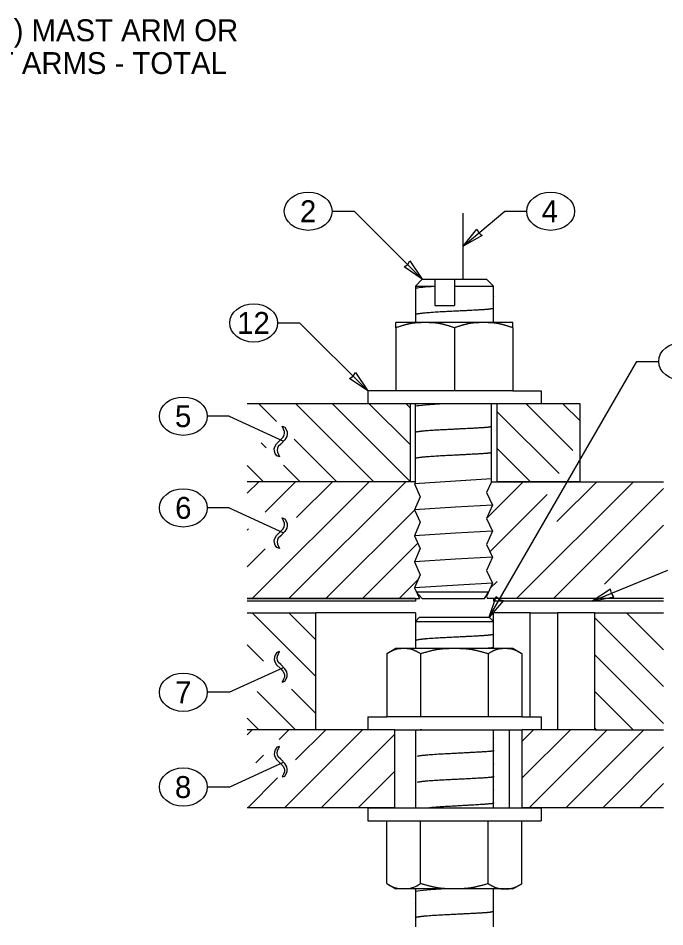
# Model space of a CAD drawing. Extents: x 99862 to 103151, y 100000 to 102076.
# Drawn here: x 100335 to 100807, y 100763 to 101428 of the extents above; entities that cross this region are included whole.
import ezdxf

# ---------------------------------------------------------------- set-up
doc = ezdxf.new("R2010")
doc.units = 0
for name, color, linetype in [('Level 15', 7, 'Continuous'), ('Level 2', 7, 'Continuous'), ('Level 20', 7, 'Continuous'), ('Level 3', 7, 'Continuous'), ('Level 4', 7, 'Continuous'), ('Level 6', 7, 'Continuous'), ('Level 62', 7, 'Continuous'), ('Level 7', 7, 'Continuous'), ('Level 9', 7, 'Continuous')]:
    doc.layers.add(name, color=color, linetype=linetype)

msp = doc.modelspace()

# ---------------------------------------------------------------- linework, layer by layer
at = {"layer": 'Level 15'}
for p, q in [((100563.94, 101286.35), (100579.94, 101286.35)), ((100579.94, 101286.35), (100629.78, 101236.72)), ((100659.59, 101260.86), (100690.09, 101286.35)), ((100690.09, 101286.35), (100706.09, 101286.35)), ((100524.09, 101204.68), (100540.09, 101204.68)), ((100540.09, 101204.68), (100589.94, 101155.05)), ((100678.61, 100989.53), (100786.59, 101176.57)), ((100786.59, 101176.57), (100802.59, 101176.57)), ((100488.68, 101136.47), (100472.68, 101136.47)), ((100488.68, 101136.47), (100528.5, 101118.31)), ((100488.68, 101069.43), (100472.68, 101069.43)), ((100488.68, 101069.43), (100528.5, 101051.27)), ((100754.07, 101001.27), (100809.22, 101023.82)), ((100488.68, 100934.6), (100528.5, 100952.76)), ((100488.68, 100934.6), (100472.68, 100934.6)), ((100488.68, 100865.26), (100528.5, 100883.43)), ((100488.68, 100865.26), (100472.68, 100865.26))]:
    msp.add_line(p, q, dxfattribs=at)
for points in [[(100659.59, 101260.86), (100669.68, 101273.31), (100671.09, 101270.47), (100673.63, 101268.57)], [(100629.78, 101236.72), (100616.47, 101245.63), (100619.16, 101247.3), (100620.82, 101250)], [(100589.94, 101155.05), (100576.62, 101163.96), (100579.31, 101165.63), (100580.97, 101168.33)], [(100754.07, 101001.27), (100769.8, 101004.37), (100767.96, 101006.95), (100767.46, 101010.08)], [(100678.61, 100989.53), (100683.8, 101004.69), (100686.1, 101002.51), (100689.14, 101001.6)]]:
    msp.add_lwpolyline(points, close=True, dxfattribs=at)
at = {"layer": 'Level 2'}
for p, q in [((100624.77, 101003.05), (100501.89, 101003.05)), ((100624.77, 101001.27), (100501.89, 101001.27)), ((100624.77, 101003.05), (100624.77, 101001.27)), ((100681.76, 101003.05), (100681.76, 101001.27)), ((100806.13, 101003.05), (100681.76, 101003.05)), ((100806.13, 101001.27), (100681.76, 101001.27))]:
    msp.add_line(p, q, dxfattribs=at)
at = {"layer": 'Level 20'}
for p, q in [((100528.5, 101126.96), (100527.36, 101129.1)), ((100527.36, 101129.1), (100529.35, 101128.39)), ((100529.35, 101128.39), (100530.43, 101126.73)), ((100526.15, 101119.19), (100527.94, 101121.01)), ((100527.94, 101121.01), (100528.91, 101122.66)), ((100529.08, 101125.33), (100528.5, 101126.96)), ((100528.91, 101122.66), (100529.17, 101123.97)), ((100529.17, 101123.97), (100529.08, 101125.33)), ((100530.78, 101121.61), (100529.43, 101119.25)), ((100530.43, 101126.73), (100531.04, 101125.04)), ((100531.15, 101123.34), (100530.78, 101121.61)), ((100531.04, 101125.04), (100531.15, 101123.34)), ((100521.68, 101112.54), (100522.04, 101114.17)), ((100522.04, 101114.17), (100523.21, 101116.34)), ((100523.21, 101116.34), (100526.15, 101119.19)), ((100524.62, 101114.39), (100523.9, 101113.08)), ((100526.33, 101116.12), (100524.62, 101114.39)), ((100529.43, 101119.25), (100526.33, 101116.12)), ((100521.8, 101110.93), (100521.68, 101112.54)), ((100522.38, 101109.25), (100521.8, 101110.93)), ((100523.48, 101107.41), (100522.38, 101109.25)), ((100525.47, 101106.7), (100523.48, 101107.41)), ((100523.9, 101113.08), (100523.67, 101111.68)), ((100523.67, 101111.68), (100523.91, 101110.05)), ((100523.91, 101110.05), (100525.47, 101106.7)), ((100528.5, 101059.92), (100527.36, 101062.06)), ((100527.36, 101062.06), (100529.35, 101061.35)), ((100529.35, 101061.35), (100530.43, 101059.68)), ((100526.15, 101052.14), (100527.94, 101053.96)), ((100527.94, 101053.96), (100528.91, 101055.62)), ((100529.08, 101058.28), (100528.5, 101059.92)), ((100528.91, 101055.62), (100529.17, 101056.93)), ((100529.17, 101056.93), (100529.08, 101058.28)), ((100530.78, 101054.57), (100529.43, 101052.21)), ((100530.43, 101059.68), (100531.04, 101058)), ((100531.15, 101056.29), (100530.78, 101054.57)), ((100531.04, 101058), (100531.15, 101056.29)), ((100522.04, 101047.13), (100523.21, 101049.3)), ((100523.21, 101049.3), (100526.15, 101052.14)), ((100524.62, 101047.35), (100523.9, 101046.04)), ((100526.33, 101049.07), (100524.62, 101047.35)), ((100529.43, 101052.21), (100526.33, 101049.07)), ((100521.68, 101045.5), (100522.04, 101047.13)), ((100521.8, 101043.89), (100521.68, 101045.5)), ((100522.38, 101042.21), (100521.8, 101043.89)), ((100523.48, 101040.37), (100522.38, 101042.21)), ((100523.9, 101046.04), (100523.67, 101044.64)), ((100523.67, 101044.64), (100523.91, 101043.01)), ((100523.91, 101043.01), (100525.47, 101039.66)), ((100525.47, 101039.66), (100523.48, 101040.37)), ((100522.38, 100961.82), (100521.8, 100960.14)), ((100523.48, 100963.66), (100522.38, 100961.82)), ((100525.47, 100964.37), (100523.48, 100963.66)), ((100523.67, 100959.39), (100523.91, 100961.02)), ((100523.91, 100961.02), (100525.47, 100964.37)), ((100521.8, 100960.14), (100521.68, 100958.53)), ((100521.68, 100958.53), (100522.04, 100956.9)), ((100522.04, 100956.9), (100523.21, 100954.73)), ((100523.21, 100954.73), (100526.15, 100951.89)), ((100523.9, 100957.99), (100523.67, 100959.39)), ((100524.62, 100956.68), (100523.9, 100957.99)), ((100526.33, 100954.96), (100524.62, 100956.68)), ((100529.43, 100951.82), (100526.33, 100954.96)), ((100526.15, 100951.89), (100527.94, 100950.07)), ((100527.94, 100950.07), (100528.91, 100948.41)), ((100528.91, 100948.41), (100529.17, 100947.1)), ((100530.78, 100949.46), (100529.43, 100951.82)), ((100531.15, 100947.73), (100530.78, 100949.46)), ((100531.04, 100946.03), (100531.15, 100947.73)), ((100528.5, 100944.11), (100527.36, 100941.97)), ((100527.36, 100941.97), (100529.35, 100942.68)), ((100529.08, 100945.75), (100528.5, 100944.11)), ((100529.17, 100947.1), (100529.08, 100945.75)), ((100529.35, 100942.68), (100530.43, 100944.35)), ((100530.43, 100944.35), (100531.04, 100946.03)), ((100525.47, 100895.04), (100523.48, 100894.33)), ((100523.91, 100891.69), (100525.47, 100895.04)), ((100521.8, 100890.81), (100521.68, 100889.19)), ((100521.68, 100889.19), (100522.04, 100887.57)), ((100522.38, 100892.49), (100521.8, 100890.81)), ((100523.48, 100894.33), (100522.38, 100892.49)), ((100523.67, 100890.06), (100523.91, 100891.69)), ((100523.9, 100888.66), (100523.67, 100890.06)), ((100524.62, 100887.34), (100523.9, 100888.66)), ((100522.04, 100887.57), (100523.21, 100885.4)), ((100523.21, 100885.4), (100526.15, 100882.55)), ((100526.33, 100885.62), (100524.62, 100887.34)), ((100526.15, 100882.55), (100527.94, 100880.73)), ((100529.43, 100882.49), (100526.33, 100885.62)), ((100530.78, 100880.12), (100529.43, 100882.49)), ((100528.5, 100874.78), (100527.36, 100872.64)), ((100527.94, 100880.73), (100528.91, 100879.08)), ((100529.08, 100876.41), (100528.5, 100874.78)), ((100528.91, 100879.08), (100529.17, 100877.77)), ((100529.17, 100877.77), (100529.08, 100876.41)), ((100529.35, 100873.35), (100530.43, 100875.01)), ((100530.43, 100875.01), (100531.04, 100876.7)), ((100531.15, 100878.4), (100530.78, 100880.12)), ((100531.04, 100876.7), (100531.15, 100878.4)), ((100527.36, 100872.64), (100529.35, 100873.35))]:
    msp.add_line(p, q, dxfattribs=at)
for centre in [(100546.44, 101286.35), (100723.59, 101286.35), (100506.59, 101204.68), (100820.09, 101176.57), (100455.18, 101136.47), (100455.18, 101069.43), (100455.18, 100934.6), (100455.18, 100865.26)]:
    msp.add_ellipse(centre, major_axis=(-17.5, 0), ratio=0.8, dxfattribs=at)
at = {"layer": 'Level 3'}
for p, q in [((100624.77, 101088.55), (100501.89, 101088.55)), ((100501.89, 101080.07), (100510.37, 101088.55)), ((100505.48, 101003.05), (100590.98, 101088.55)), ((100514.94, 101066.25), (100537.24, 101088.55)), ((100532.35, 101003.05), (100617.85, 101088.55)), ((100537.96, 101062.4), (100564.11, 101088.55)), ((100624.77, 101088.55), (100624.11, 101087.09)), ((100680.41, 101088.55), (100676.83, 101080.61)), ((100676.98, 101061.92), (100703.61, 101088.55)), ((100680.41, 101088.55), (100806.13, 101088.55)), ((100698.72, 101003.05), (100784.21, 101088.55)), ((100728.17, 101059.38), (100757.34, 101088.55)), ((100624.11, 101087.09), (100628.38, 101077.59)), ((100676.83, 101080.61), (100681.11, 101071.33)), ((100725.59, 101003.05), (100806.13, 101083.6)), ((100628.38, 101077.59), (100624.11, 101068.07)), ((100679.27, 101037.34), (100721.16, 101079.24)), ((100559.22, 101003.05), (100624.77, 101068.6)), ((100624.11, 101068.07), (100628.38, 101058.86)), ((100681.11, 101071.33), (100676.83, 101061.59)), ((100676.83, 101061.59), (100681.11, 101052.37)), ((100501.89, 101053.2), (100502.86, 101054.17)), ((100628.38, 101058.86), (100624.11, 101049.03)), ((100762.94, 101013.54), (100806.13, 101056.73)), ((100624.11, 101049.03), (100628.38, 101039.82)), ((100681.11, 101052.37), (100676.83, 101042.62)), ((100586.09, 101003.05), (100626.63, 101043.6)), ((100676.83, 101042.62), (100681.11, 101033.34)), ((100501.89, 101026.33), (100514.93, 101039.37)), ((100628.38, 101039.82), (100624.11, 101030.07)), ((100624.11, 101030.07), (100628.38, 101020.57)), ((100681.11, 101033.34), (100676.83, 101023.59)), ((100676.83, 101023.59), (100681.11, 101014.4)), ((100612.96, 101003.05), (100626.68, 101016.78)), ((100628.38, 101020.57), (100624.11, 101011.04)), ((100681.11, 101014.4), (100676.83, 101004.57)), ((100679.5, 101010.71), (100684.46, 101015.67)), ((100624.11, 101011.04), (100627.71, 101003.05)), ((100501.89, 101003.05), (100627.71, 101003.05)), ((100676.83, 101004.57), (100677.54, 101003.05)), ((100806.13, 101003.05), (100677.54, 101003.05)), ((100501.89, 100992.66), (100552.03, 100992.66)), ((100552.03, 100907.17), (100552.03, 100992.66)), ((100755.89, 100907.17), (100755.89, 100992.66)), ((100755.89, 100992.66), (100806.13, 100992.66)), ((100552.03, 100907.17), (100501.89, 100907.17)), ((100755.89, 100907.17), (100806.13, 100907.17))]:
    msp.add_line(p, q, dxfattribs=at)
at = {"layer": 'Level 4'}
for p, q in [((100501.89, 100903.54), (100505.52, 100907.17)), ((100525.17, 100899.95), (100532.39, 100907.17)), ((100529.13, 100850.17), (100586.13, 100907.17)), ((100537.17, 100885.08), (100559.26, 100907.17)), ((100609.7, 100907.17), (100552.03, 100907.17)), ((100556, 100850.17), (100609.7, 100903.87)), ((100609.7, 100850.17), (100609.7, 100907.17)), ((100693.57, 100850.17), (100693.57, 100907.17)), ((100755.89, 100907.17), (100702.9, 100907.17)), ((100702.9, 100850.17), (100702.9, 100907.17)), ((100702.9, 100898.92), (100711.15, 100907.17)), ((100702.9, 100872.05), (100738.02, 100907.17)), ((100707.89, 100850.17), (100764.89, 100907.17)), ((100734.76, 100850.17), (100791.76, 100907.17)), ((100761.63, 100850.17), (100806.13, 100894.67)), ((100508.17, 100882.95), (100513.79, 100888.57)), ((100582.87, 100850.17), (100609.7, 100877)), ((100502.26, 100850.17), (100524.09, 100872)), ((100788.5, 100850.17), (100806.13, 100867.8)), ((100609.7, 100850.17), (100501.89, 100850.17)), ((100806.13, 100850.17), (100702.9, 100850.17))]:
    msp.add_line(p, q, dxfattribs=at)
at = {"layer": 'Level 6'}
msp.add_line((100682.1, 100764), (100681.74, 100763.93), dxfattribs=at)
at = {"layer": 'Level 62'}
for points in [[(100680.41, 101090.57), (100624.13, 101087.13)], [(100681.11, 101071.33), (100654.11, 101069.92), (100624.11, 101068.07)], [(100681.11, 101052.37), (100654.07, 101050.92), (100624.11, 101049.03)], [(100681.11, 101033.34), (100653.99, 101031.9), (100624.11, 101030.07)], [(100681.11, 101014.4), (100655.94, 101013.01), (100624.11, 101011.04)]]:
    msp.add_lwpolyline(points, dxfattribs=at)
for points, degree in [([(100639, 101231.3), (100631.68, 101230.82), (100627.1, 101230.4), (100625.47, 101230.04)], 3), ([(100681.74, 101224.33), (100681.89, 101224.24), (100681.89, 101224.15), (100681.74, 101224.05)], 3), ([(100681.05, 101215.08), (100679.43, 101214.69), (100675.63, 101214.37), (100670.57, 101214.1), (100652.29, 101213.09), (100630.39, 101212.14), (100625.47, 101211.02)], 4), ([(100681.74, 101205.31), (100681.93, 101205.18), (100681.84, 101205.05), (100681.49, 101204.92)], 3), ([(100646.7, 101145.55), (100635.04, 101144.86), (100627.17, 101144.27), (100624.83, 101143.76)], 3), ([(100680.41, 101128.77), (100678.55, 101128.31), (100673.86, 101127.95), (100667.71, 101127.65), (100649.66, 101126.71), (100629.45, 101125.75), (100624.83, 101124.73)], 4), ([(100680.41, 101109.79), (100678.65, 101109.36), (100674.32, 101109.01), (100668.62, 101108.73), (100650.46, 101107.76), (100629.57, 101106.73), (100624.83, 101105.7)], 4), ([(100681.05, 100976.7), (100679.43, 100976.31), (100675.63, 100975.99), (100670.57, 100975.72), (100652.29, 100974.71), (100630.39, 100973.76), (100625.47, 100972.64)], 4), ([(100681.74, 100967.74), (100682.43, 100967.26), (100679.73, 100966.87), (100674.76, 100966.54)], 3), ([(100629.38, 100907.17), (100627.83, 100907.01), (100626.77, 100906.86), (100626.16, 100906.73)], 3), ([(100681.74, 100901.23), (100681.87, 100901.15), (100681.87, 100901.06), (100681.74, 100900.97)], 3), ([(100682.43, 100892), (100681.68, 100891.52), (100677.63, 100891.13), (100671.72, 100890.82), (100653.45, 100889.79), (100631.23, 100888.78), (100626.16, 100887.7)], 4), ([(100681.74, 100891.73), (100681.84, 100891.65), (100681.84, 100891.57), (100681.74, 100891.5)], 3), ([(100681.74, 100882.25), (100681.87, 100882.16), (100681.87, 100882.08), (100681.74, 100881.99)], 3), ([(100682.43, 100872.98), (100681.6, 100872.45), (100677.02, 100872.02), (100670.41, 100871.66), (100652.18, 100870.68), (100630.92, 100869.74), (100626.16, 100868.68)], 4), ([(100681.74, 100872.74), (100681.88, 100872.65), (100681.88, 100872.56), (100681.74, 100872.47)], 3), ([(100681.74, 100863.22), (100681.88, 100863.13), (100681.88, 100863.04), (100681.74, 100862.95)], 3), ([(100681.74, 100853.72), (100682.28, 100853.34), (100680.52, 100853.04), (100677.18, 100852.78), (100667.62, 100852.05), (100649.74, 100851.2), (100635.17, 100850.17)], 4), ([(100624.75, 100789.62), (100624.66, 100789.57), (100624.66, 100789.51), (100624.75, 100789.45)], 3), ([(100647.77, 100790.8), (100635.91, 100790.09), (100627.78, 100789.45), (100625.43, 100788.89)], 3), ([(100624.75, 100780.16), (100624.61, 100780.1), (100624.6, 100780.03), (100624.75, 100779.95)], 3), ([(100624.75, 100770.65), (100624.67, 100770.6), (100624.67, 100770.54), (100624.75, 100770.48)], 3), ([(100681.01, 100773.99), (100679.15, 100773.54), (100674.46, 100773.18), (100668.31, 100772.88), (100650.25, 100771.94), (100630.05, 100770.97), (100625.43, 100769.96)], 4)]:
    msp.add_open_spline(points, degree=degree, dxfattribs=at)
at = {"layer": 'Level 7'}
for p, q in [((100505.42, 100992.66), (100552.03, 100946.05)), ((100532.29, 100992.66), (100552.03, 100972.92)), ((100708.68, 100992.66), (100681.74, 100992.66)), ((100708.68, 100916.67), (100708.68, 100992.66)), ((100708.68, 100992.66), (100728.83, 100992.66)), ((100728.83, 100907.17), (100728.83, 100992.66)), ((100755.89, 100992.66), (100728.83, 100992.66)), ((100755.89, 100988.95), (100806.13, 100938.71)), ((100779.04, 100992.66), (100806.13, 100965.57)), ((100805.91, 100992.66), (100806.13, 100992.44)), ((100501.89, 100969.32), (100513.83, 100957.39)), ((100755.89, 100962.08), (100806.13, 100911.84)), ((100509.19, 100935.16), (100537.18, 100907.17)), ((100534.29, 100936.92), (100552.03, 100919.18)), ((100755.89, 100935.22), (100783.93, 100907.17)), ((100501.89, 100915.59), (100510.31, 100907.17)), ((100755.89, 100908.35), (100757.06, 100907.17))]:
    msp.add_line(p, q, dxfattribs=at)
at = {"layer": 'Level 9'}
for p, q in [((100659.59, 101236.72), (100659.59, 101284.99)), ((100629.78, 101236.72), (100624.75, 101231.68)), ((100629.78, 101236.72), (100659.59, 101236.72)), ((100639, 101236.72), (100639, 101217.43)), ((100653.25, 101236.72), (100653.25, 101217.43)), ((100659.59, 101236.72), (100676.71, 101236.72)), ((100681.74, 101231.68), (100676.71, 101236.72)), ((100624.75, 101231.68), (100624.75, 101204.92)), ((100624.75, 101231.68), (100639, 101231.68)), ((100653.25, 101231.68), (100681.74, 101231.68)), ((100681.74, 101204.92), (100681.74, 101231.68)), ((100639, 101217.43), (100653.25, 101217.43)), ((100681.74, 101204.92), (100610.53, 101204.92)), ((100610.53, 101201.11), (100610.53, 101155.05)), ((100632.91, 101204.92), (100630.89, 101204.92)), ((100653.27, 101201.11), (100653.27, 101155.05)), ((100675.41, 101204.92), (100673.86, 101204.92)), ((100696.01, 101204.92), (100681.74, 101204.92)), ((100696.01, 101201.1), (100696.01, 101155.05)), ((100589.94, 101155.05), (100589.94, 101145.55)), ((100696.01, 101155.05), (100589.94, 101155.05)), ((100696.01, 101155.05), (100716.6, 101155.05)), ((100716.6, 101155.05), (100716.6, 101155.05)), ((100716.6, 101155.05), (100716.6, 101145.55)), ((100589.94, 101145.55), (100501.89, 101145.55)), ((100510.46, 101145.55), (100523.38, 101132.63)), ((100537.33, 101145.55), (100594.33, 101088.55)), ((100564.2, 101145.55), (100621.19, 101088.55)), ((100621.21, 101145.55), (100589.94, 101145.55)), ((100591.07, 101145.55), (100621.21, 101115.41)), ((100617.93, 101145.55), (100621.21, 101142.28)), ((100684.62, 101145.55), (100621.21, 101145.55)), ((100621.21, 101088.55), (100621.21, 101145.55)), ((100624.77, 101088.55), (100624.77, 101145.55)), ((100680.41, 101088.55), (100680.41, 101145.55)), ((100684.62, 101088.55), (100684.62, 101145.55)), ((100716.6, 101145.55), (100684.62, 101145.55)), ((100705.72, 101145.55), (100739.78, 101111.49)), ((100745.08, 101145.55), (100716.6, 101145.55)), ((100732.59, 101145.55), (100745.08, 101133.05)), ((100745.08, 101088.55), (100745.08, 101145.55)), ((100684.62, 101139.78), (100729.95, 101094.45)), ((100512.18, 101116.96), (100515.83, 101113.31)), ((100536.25, 101119.76), (100567.46, 101088.55)), ((100684.62, 101112.91), (100708.98, 101088.55)), ((100528.37, 101100.77), (100540.59, 101088.55)), ((100501.89, 101100.38), (100513.72, 101088.55)), ((100621.21, 101088.55), (100501.89, 101088.55)), ((100745.08, 101088.55), (100684.62, 101088.55)), ((100629.78, 101003.05), (100625.44, 101008.09)), ((100625.44, 101008.09), (100678.36, 101008.09)), ((100675.25, 101003.05), (100678.36, 101008.09)), ((100629.78, 101003.05), (100675.25, 101003.05)), ((100624.75, 100992.66), (100552.03, 100992.66)), ((100624.75, 100992.66), (100624.75, 100986.39)), ((100627.88, 100989.53), (100624.75, 100986.39)), ((100627.88, 100989.53), (100678.61, 100989.53)), ((100678.61, 100989.53), (100681.74, 100986.39)), ((100681.74, 100986.39), (100681.74, 100992.66)), ((100624.75, 100986.39), (100624.75, 100966.54)), ((100624.75, 100986.39), (100681.74, 100986.39)), ((100681.74, 100966.54), (100681.74, 100986.39)), ((100610.52, 100966.54), (100603.9, 100962.72)), ((100603.91, 100962.72), (100603.91, 100916.67)), ((100624.75, 100966.54), (100610.52, 100966.54)), ((100616.53, 100966.54), (100615.97, 100966.54)), ((100652.21, 100966.54), (100624.75, 100966.54)), ((100628.58, 100962.73), (100628.58, 100916.67)), ((100654.32, 100966.54), (100652.21, 100966.54)), ((100681.74, 100966.54), (100654.32, 100966.54)), ((100677.94, 100962.73), (100677.94, 100916.67)), ((100696.01, 100966.54), (100681.74, 100966.54)), ((100690.86, 100966.54), (100689.69, 100966.54)), ((100702.61, 100962.73), (100696.01, 100966.54)), ((100702.61, 100962.73), (100702.61, 100916.67)), ((100589.94, 100916.67), (100589.94, 100907.17)), ((100589.94, 100916.67), (100603.91, 100916.67)), ((100702.61, 100916.67), (100603.91, 100916.67)), ((100702.61, 100916.67), (100716.6, 100916.67)), ((100716.6, 100916.67), (100716.6, 100907.17)), ((100609.7, 100907.17), (100624.75, 100907.17)), ((100624.75, 100907.17), (100624.75, 100850.17)), ((100624.75, 100907.17), (100681.74, 100907.17)), ((100681.74, 100850.17), (100681.74, 100907.17)), ((100681.74, 100907.17), (100702.9, 100907.17)), ((100589.94, 100850.17), (100589.94, 100840.67)), ((100589.94, 100850.17), (100624.75, 100850.17)), ((100624.75, 100850.17), (100681.74, 100850.17)), ((100681.74, 100850.17), (100716.6, 100850.17)), ((100716.6, 100850.17), (100716.6, 100840.67)), ((100589.94, 100840.67), (100589.94, 100840.67)), ((100589.94, 100840.67), (100603.91, 100840.67)), ((100603.91, 100840.67), (100702.61, 100840.67)), ((100603.91, 100794.62), (100603.91, 100840.67)), ((100628.58, 100794.62), (100628.58, 100840.67)), ((100677.94, 100794.61), (100677.94, 100840.67)), ((100702.61, 100794.61), (100702.61, 100840.67)), ((100702.61, 100840.67), (100716.6, 100840.67)), ((100603.9, 100794.62), (100610.52, 100790.8)), ((100624.75, 100790.8), (100610.52, 100790.8)), ((100681.74, 100790.8), (100624.75, 100790.8)), ((100624.75, 100790.8), (100624.75, 100763.06)), ((100689.83, 100790.8), (100681.74, 100790.8)), ((100681.74, 100763.06), (100681.74, 100790.8)), ((100689.83, 100790.8), (100690.73, 100790.8)), ((100696.01, 100790.8), (100690.73, 100790.8)), ((100696.01, 100790.8), (100702.61, 100794.61))]:
    msp.add_line(p, q, dxfattribs=at)
for points, degree in [([(100610.53, 101201.11), (100610.53, 101203.33), (100610.53, 101204.81), (100610.53, 101204.92)], 2), ([(100630.89, 101204.92), (100623.96, 101204.79), (100617.18, 101203.33), (100610.53, 101201.11)], 2), ([(100653.27, 101201.11), (100646.6, 101203.33), (100639.84, 101204.79), (100632.91, 101204.92)], 2), ([(100673.86, 101204.92), (100666.85, 101204.82), (100660, 101203.35), (100653.27, 101201.11)], 2), ([(100696.01, 101201.1), (100689.27, 101203.35), (100682.42, 101204.82), (100675.41, 101204.92)], 2), ([(100696.01, 101204.92), (100696.01, 101204.92), (100696.01, 101204.92), (100696.01, 101204.92)], 2), ([(100696.01, 101201.1), (100696.01, 101203.42), (100696.01, 101204.92), (100696.01, 101204.92)], 2), ([(100615.97, 100966.54), (100611.86, 100966.48), (100607.84, 100965), (100603.91, 100962.72)], 2), ([(100628.58, 100962.73), (100624.64, 100965), (100620.64, 100966.48), (100616.53, 100966.54)], 2), ([(100652.21, 100966.54), (100644.2, 100966.43), (100636.23, 100964.94), (100628.58, 100962.73)], 2), ([(100677.94, 100962.73), (100670.25, 100964.95), (100662.3, 100966.43), (100654.32, 100966.54)], 2), ([(100689.69, 100966.54), (100685.69, 100966.41), (100681.78, 100964.95), (100677.94, 100962.73)], 2), ([(100702.61, 100962.73), (100698.76, 100964.95), (100694.86, 100966.41), (100690.86, 100966.54)], 2), ([(100603.91, 100794.62), (100607.93, 100792.29), (100612.02, 100790.81), (100620.42, 100790.8), (100624.55, 100792.29), (100628.58, 100794.62)], 3), ([(100653.27, 100790.8), (100644.91, 100790.8), (100636.57, 100792.31), (100628.58, 100794.62)], 2), ([(100677.94, 100794.61), (100669.91, 100792.3), (100661.61, 100790.8), (100653.27, 100790.8)], 2), ([(100677.94, 100794.61), (100681.83, 100792.36), (100685.78, 100790.9), (100689.83, 100790.8)], 2), ([(100690.73, 100790.8), (100694.77, 100790.9), (100698.73, 100792.37), (100702.61, 100794.61)], 2)]:
    msp.add_open_spline(points, degree=degree, dxfattribs=at)

# ---------------------------------------------------------------- texts
at = {"layer": 'Level 20'}
for s, p in [("50' (FT) LUMINAIRE W/ 1 x 16' (FT) (MAX.) MAST ARM OR ", (99922.47, 101410.69)), ("40' (FT) LUMINAIRE W/ 2 x 16' (FT) MAST ARMS - TOTAL", (99922.47, 101386.69)), ('2', (100540.45, 101278.35)), ('4', (100717.08, 101278.35)), ('12', (100494.56, 101196.68)), ('5', (100449.08, 101128.48)), ('6', (100449.23, 101061.43)), ('7', (100449.23, 100926.6)), ('8', (100449.08, 100857.27))]:
    msp.add_text(s, height=16, dxfattribs=at).set_placement(p)

doc.saveas('drawing.dxf')
